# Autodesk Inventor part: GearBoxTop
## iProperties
Part Number: GearBoxTop
Document SubType Name: Modeling
Created: 2003-11
Designer: ales
Manufacturer: Standard
Standards Organization: Custom
Density: 1 g/cm^3
Mass: 502.72 g
Surface Area: 1167.52 cm^2
Volume: 502.72 cm^3
Control State: 0
Master: False
Checked Out: False
Shininess: 64.0
Length Units: 11269
Angle Units: 11279
Time Units: 11290
Mass Units: 11283
Length Display Precision: 3
Angle Display Precision: 2
Compacted: True
Density: 0.0
Volumn: 0.0
Area: 0.0
PropertySet Name: Model Information
Author: ales
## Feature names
1. Extrusion2
2. Shell2
3. Extrusion5
4. Extrusion6
5. Extrusion7
6. Extrusion3
7. Extrusion4
8. Extrusion8
9. Extrusion9
10. Fillet1
11. Fillet2
12. Fillet3
13. Fillet4
14. Fillet6
15. Hole2
16. Hole3
17. Hole4
18. Hole5
19. Hole6
20. Hole7
21. Fillet7
22. Fillet10
23. Fillet8
24. Fillet9
25. Fillet11
26. Chamfer1
